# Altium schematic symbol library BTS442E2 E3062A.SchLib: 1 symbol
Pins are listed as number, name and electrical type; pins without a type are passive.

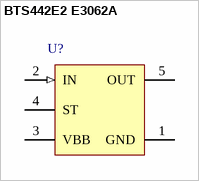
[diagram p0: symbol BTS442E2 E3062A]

## BTS442E2 E3062A
designator U?
Smart High-Side Power Switch, 1 Channel, 7.5 A Load Current, -40 to 150 degC, PG-TO263-5-2, Reel, Green; Manufacturer: Infineon; PartNumber: BTS442E2 E3062A; Channels: 1; Green: TRUE; Group: Automotive Qualified; Load Current (typ): 7.5 A; Recommended Operating Voltage Max.: 42 V; Recommended Operating Voltage Min.: 4.5 V; RON @ 25degreesC: 18 mOhm; RON(max) @ 150degreesC: 35 mOhm
footprint INF-PG-TO263-5-2_N (DPAK, 5-Leads, Body 10x9.25mm, Pitch 1.7mm, IPC Medium Density)
footprint INF-PG-TO263-5-2_L (DPAK, 5-Leads, Body 10x9.25mm, Pitch 1.7mm, IPC High Density)
footprint INF-PG-TO263-5-2_M (DPAK, 5-Leads, Body 10x9.25mm, Pitch 1.7mm, IPC Low Density)
pins: 1 GND (power) "Logic ground.", 2 IN (in) "Input, activates the power switch in case of logical signal.", 3 VBB (power) "Positive power supply voltage, the tab is shorted to this pin", 4 ST (oc) "Diagnostic feedback", 5 OUT (power) "Output to the load."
